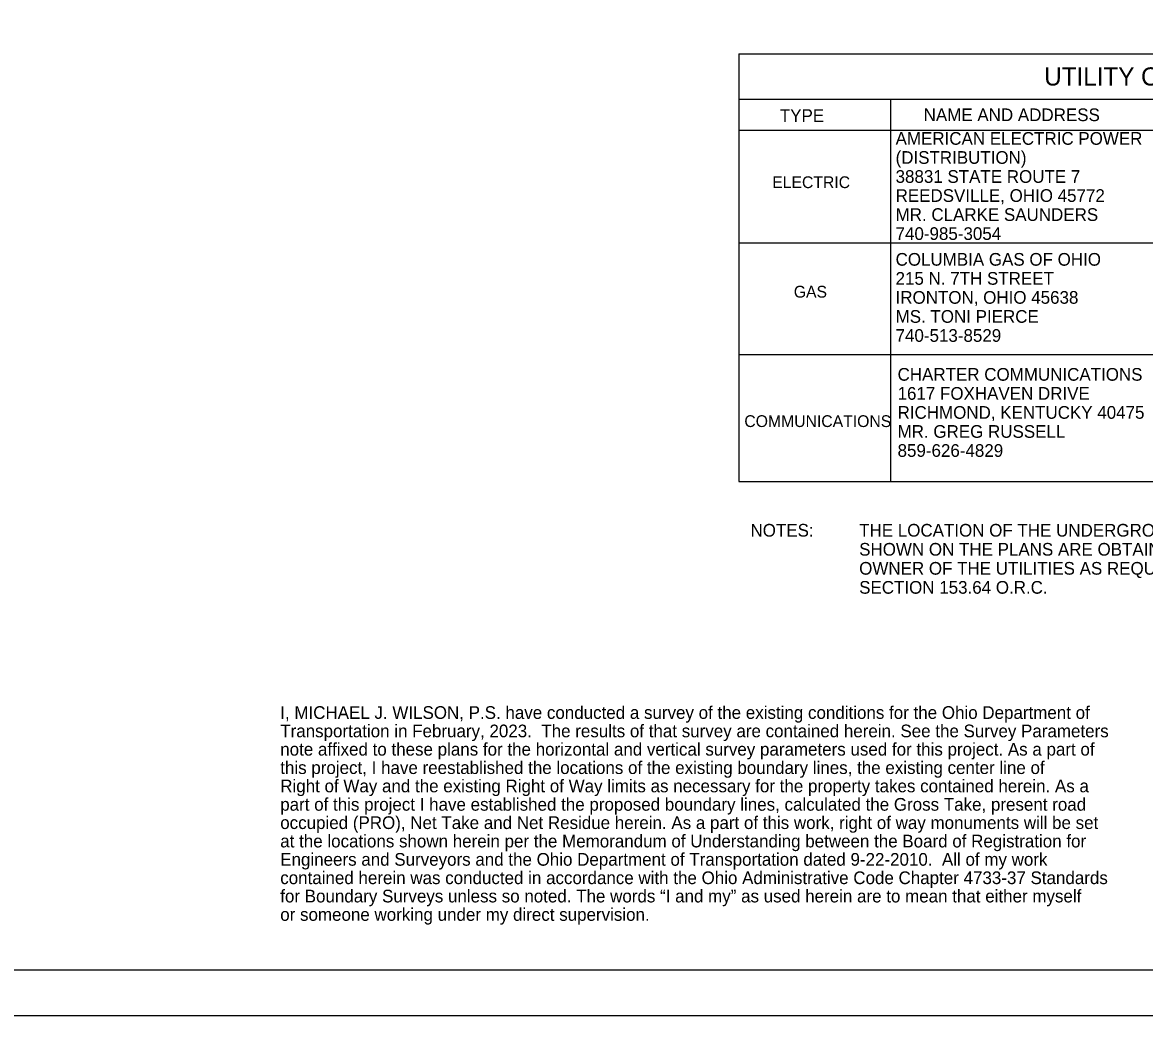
# Model space of a CAD drawing. Extents: x 0 to 34, y 0 to 22.
# Drawn here: x 14.34 to 26.73, y 0 to 10.96 of the extents above; entities that cross this region are included whole.
import ezdxf

# ---------------------------------------------------------------- set-up
doc = ezdxf.new("R2010")
doc.units = 0
for name, color, linetype in [('SH_Border', 7, 'Continuous'), ('SH_Cut_Line', 7, 'Continuous'), ('SH_Data', 7, 'Continuous'), ('SH_Text', 7, 'Continuous')]:
    doc.layers.add(name, color=color, linetype=linetype)

msp = doc.modelspace()

# ---------------------------------------------------------------- linework, layer by layer
at = {"layer": 'SH_Border'}
msp.add_lwpolyline([(1.5, 21.5), (33.5, 21.5), (33.5, 0.5), (1.5, 0.5)], close=True, dxfattribs=at)
at = {"layer": 'SH_Cut_Line'}
msp.add_lwpolyline([(0, 0), (34, 0), (34, 22), (0, 22)], close=True, dxfattribs=at)
at = {"layer": 'SH_Data'}
for p, q in [((22.246, 10.611), (31.226, 10.611)), ((22.246, 10.611), (22.246, 5.892)), ((22.246, 10.111), (31.226, 10.111)), ((23.923, 10.111), (23.923, 5.892)), ((22.246, 9.77), (31.226, 9.77)), ((22.246, 8.524), (31.226, 8.524)), ((22.246, 7.294), (31.226, 7.294)), ((22.246, 5.892), (31.226, 5.892))]:
    msp.add_line(p, q, dxfattribs=at)

# ---------------------------------------------------------------- texts
for s, p in [('ELECTRIC', (22.616, 9.129)), ('GAS', (22.854, 7.921)), ('COMMUNICATIONS', (22.308, 6.493))]:
    msp.add_text(s, height=0.13, dxfattribs=at).set_placement(p)
at = {"layer": 'SH_Text'}
for s, height, p in [('UTILITY OWNERS', 0.2, (25.619, 10.261)), ('TYPE', 0.14, (22.7, 9.859)), ('NAME AND ADDRESS', 0.14, (24.288, 9.868)), ('AMERICAN ELECTRIC POWER', 0.14, (23.978, 9.607)), ('(DISTRIBUTION)', 0.14, (23.978, 9.397)), ('38831 STATE ROUTE 7', 0.14, (23.978, 9.187)), ('REEDSVILLE, OHIO 45772', 0.14, (23.978, 8.977)), ('MR. CLARKE SAUNDERS', 0.14, (23.978, 8.767)), ('740-985-3054', 0.14, (23.978, 8.557)), ('COLUMBIA GAS OF OHIO', 0.14, (23.978, 8.273)), ('215 N. 7TH STREET', 0.14, (23.978, 8.063)), ('IRONTON, OHIO 45638', 0.14, (23.978, 7.853)), ('MS. TONI PIERCE', 0.14, (23.978, 7.643)), ('740-513-8529', 0.14, (23.978, 7.433)), ('CHARTER COMMUNICATIONS', 0.14, (24, 7.004)), ('1617 FOXHAVEN DRIVE', 0.14, (24, 6.794)), ('RICHMOND, KENTUCKY 40475', 0.14, (24, 6.584)), ('MR. GREG RUSSELL', 0.14, (24, 6.374)), ('859-626-4829', 0.14, (24, 6.164)), ('NOTES:', 0.14, (22.376, 5.284)), ('THE LOCATION OF THE UNDERGROUND UTILITIES', 0.14, (23.576, 5.284)), ('SHOWN ON THE PLANS ARE OBTAINED FROM THE', 0.14, (23.576, 5.074)), ('OWNER OF THE UTILITIES AS REQUIRED BY', 0.14, (23.576, 4.864)), ('SECTION 153.64 O.R.C.', 0.14, (23.576, 4.654)), ('I, MICHAEL J. WILSON, P.S. have conducted a survey of the existing conditions for the Ohio Department of', 0.14, (17.184, 3.273)), ('Transportation in February, 2023.  The results of that survey are contained herein. See the Survey Parameters', 0.14, (17.184, 3.07)), ('note affixed to these plans for the horizontal and vertical survey parameters used for this project. As a part of', 0.14, (17.184, 2.868)), ('this project, I have reestablished the locations of the existing boundary lines, the existing center line of ', 0.14, (17.184, 2.665)), ('Right of Way and the existing Right of Way limits as necessary for the property takes contained herein. As a ', 0.14, (17.184, 2.463)), ('part of this project I have established the proposed boundary lines, calculated the Gross Take, present road ', 0.14, (17.184, 2.26)), ('occupied (PRO), Net Take and Net Residue herein. As a part of this work, right of way monuments will be set ', 0.14, (17.184, 2.058)), ('at the locations shown herein per the Memorandum of Understanding between the Board of Registration for ', 0.14, (17.184, 1.855)), ('Engineers and Surveyors and the Ohio Department of Transportation dated 9-22-2010.  All of my work ', 0.14, (17.184, 1.653)), ('contained herein was conducted in accordance with the Ohio Administrative Code Chapter 4733-37 Standards ', 0.14, (17.184, 1.45)), ('for Boundary Surveys unless so noted. The words “I and my” as used herein are to mean that either myself ', 0.14, (17.184, 1.248)), ('or someone working under my direct supervision.', 0.14, (17.184, 1.045))]:
    msp.add_text(s, height=height, dxfattribs=at).set_placement(p)

doc.saveas('drawing.dxf')
